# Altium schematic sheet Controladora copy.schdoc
size 711 x 428 mm
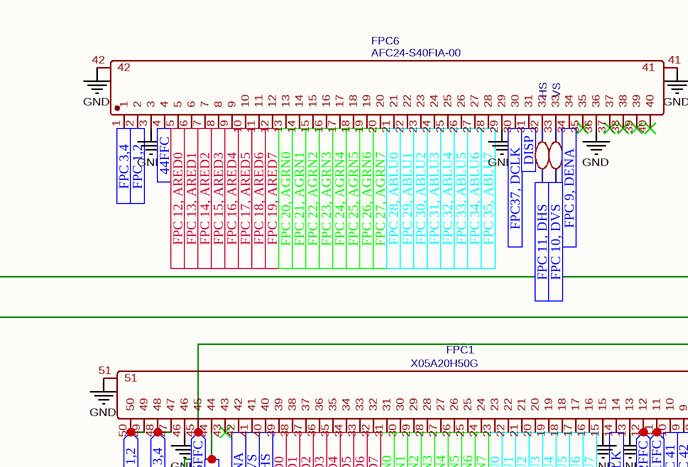
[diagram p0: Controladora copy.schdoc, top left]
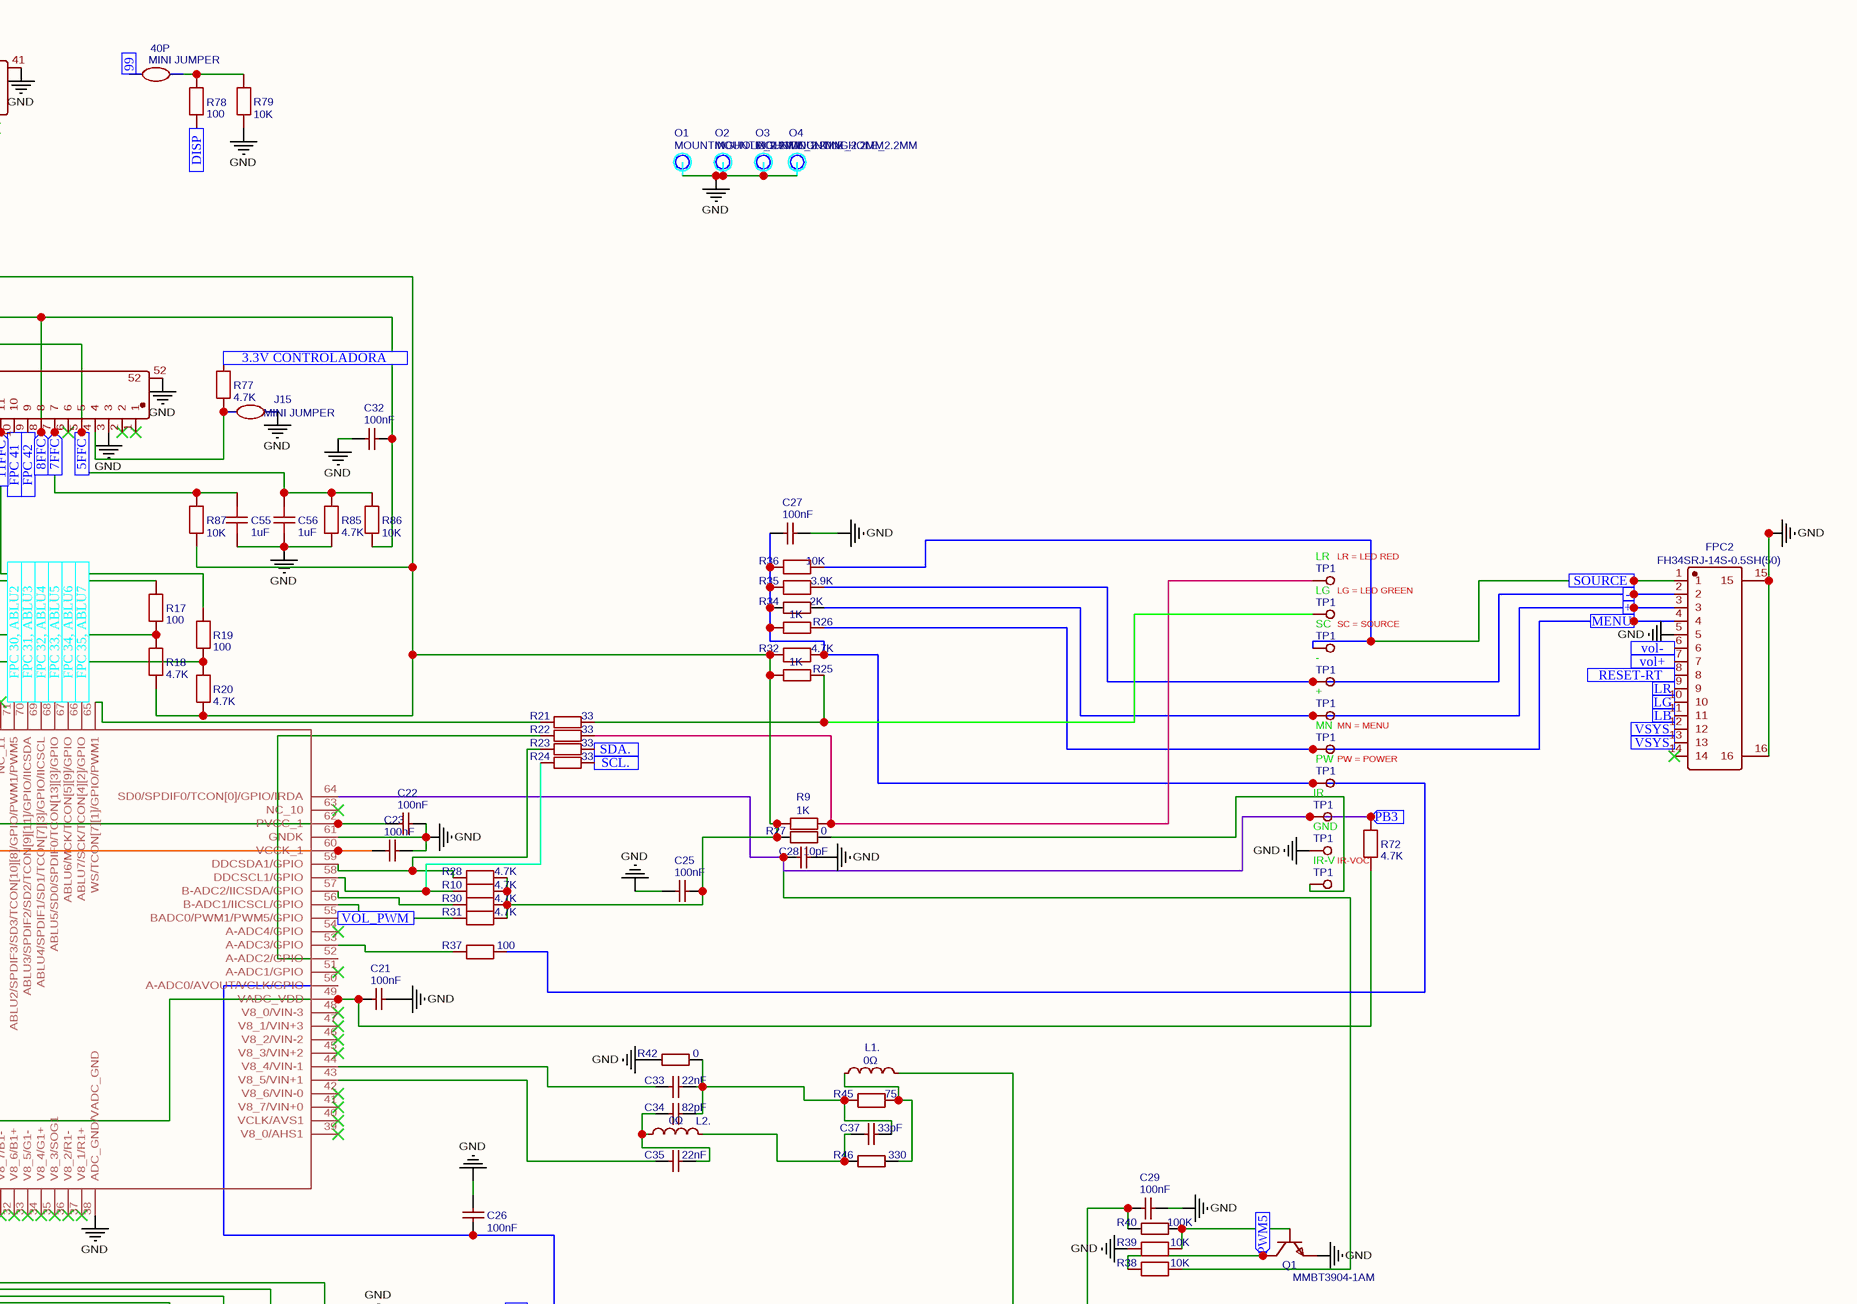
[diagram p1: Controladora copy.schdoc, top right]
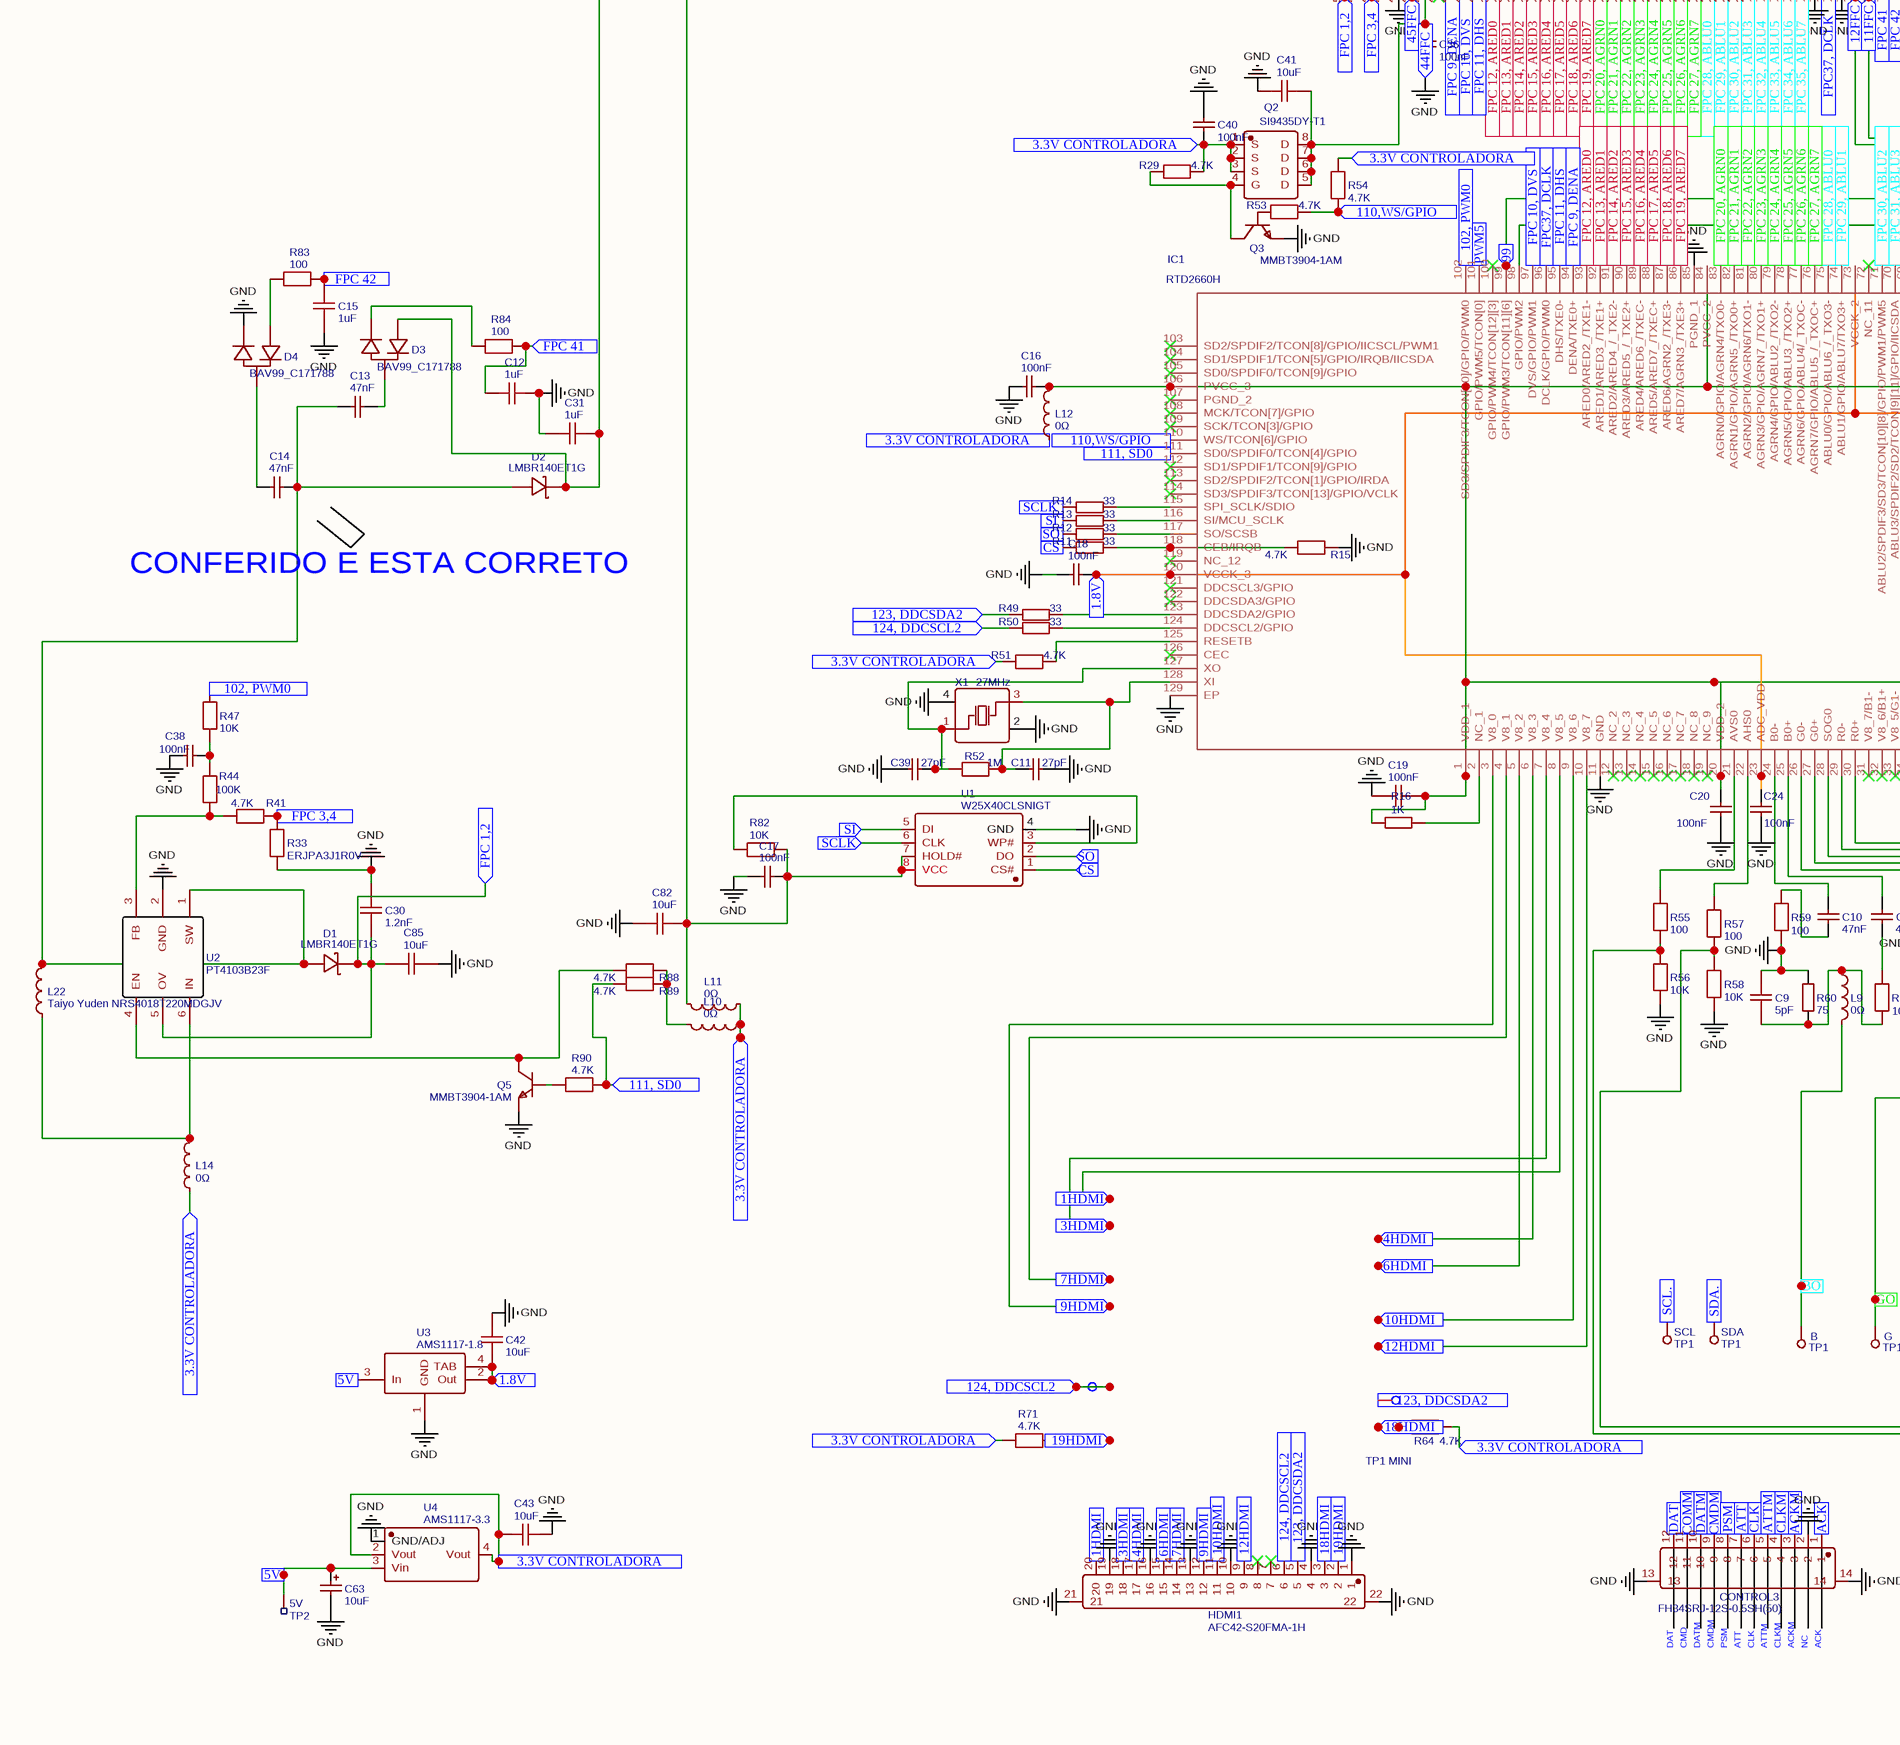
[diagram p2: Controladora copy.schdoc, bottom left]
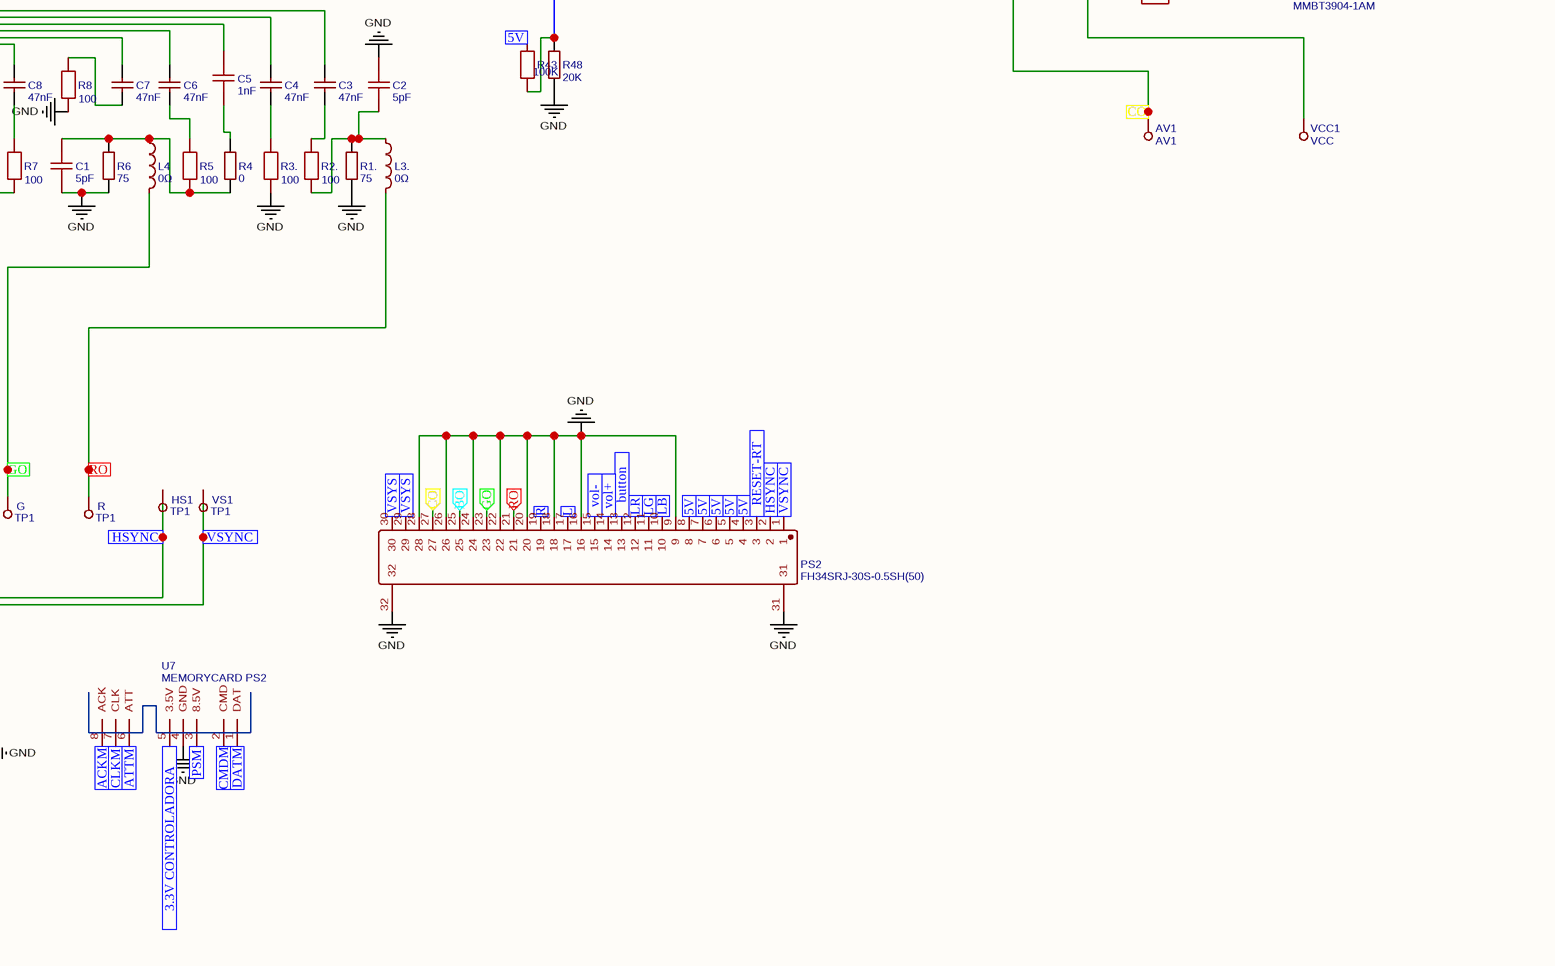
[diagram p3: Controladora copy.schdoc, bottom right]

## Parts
5V  TP2  [TP2]
40P  MINI JUMPER  [MINI JUMPER]
+  TP1  [TP1]
-  TP1  [TP1]
AV1  AV1  [TP1]
B  TP1  [TP1]
C1  5pF  [C0402]
C2  5pF  [C0402]
C3  47nF  [C0402]
C4  47nF  [C0402]
C5  1nF  [C0402]
C6  47nF  [C0402]
C7  47nF  [C0402]
C8  47nF  [C0402]
C9  5pF  [C0402]
C10  47nF  [C0402]
C11  27pF  [C0402]
C12  1uF  [C0402]
C13  47nF  [C0402]
C14  47nF  [C0402]
C15  1uF  [C0402]
C16  100nF  [C0402]
C17  100nF  [C0402]
C18  100nF  [C0402]
C19  100nF  [C0402]
C20  100nF  [C0402]
C21  100nF  [C0402]
C22  100nF  [C0402]
C23  100nF  [C0402]
C24  100nF  [C0402]
C25  100nF  [C0402]
C26  100nF  [C0402]
C27  100nF  [C0402]
C28  10pF  [C0402]
C29  100nF  [C0402]
C30  1.2nF  [C0402]
C31  1uF  [C0402]
C32  100nF  [C0402]
C33  22nF  [C0402]
C34  82pF  [C0402]
C35  22nF  [C0402]
C36  100nF  [C0402]
C37  33pF  [C0402]
C38  100nF  [C0402]
C39  27pF  [C0402]
C40  100nF  [C0402]
C41  10uF  [C0603]
C42  10uF  [C0603]
C43  10uF  [C0603]
C55  1uF  [C0402]
C56  1uF  [C0402]
C63  10uF  [CAP-SMD_L3.2-W1.6-R-RD]
C82  10uF  [C0603]
C85  10uF  [C0603]
CONTROL3  FH34SRJ-12S-0.5SH(50)  [FFC-SMD_12P-P0.50_FH34SRJ-12S-0.5SH]
D1  LMBR140ET1G  [SOD-323HE_L2.0-W1.4-LS2.5-RD]
D2  LMBR140ET1G  [SOD-323HE_L2.0-W1.4-LS2.5-RD]
D3  BAV99_C171788  [SOT-23-3_L2.9-W1.3-P1.90-LS2.4-BR]
D4  BAV99_C171788  [SOT-23-3_L2.9-W1.3-P1.90-LS2.4-BR]
FPC1  X05A20H50G  [FPC-SMD_50P-P0.50_X05A20H50G]
FPC2  FH34SRJ-14S-0.5SH(50)  [FFC-SMD_14P-P0.50_FH34SRJ-14S-0.5SH]
FPC6  AFC24-S40FIA-00  [FPC-SMD_P0.50-40P_QCHF-SM-H2.0]
G  TP1  [TP1]
GND  TP1  [TP1]
HDMI1  AFC42-S20FMA-1H  [FFC-SMD_20P-P0.50_AFC42-S20FMA-1H]
HS  MINI JUMPER  [MINI JUMPER]  (value not drawn)
HS1  TP1  [TP1]
IC1  RTD2660H  [RTD2660H]
IR  TP1  [TP1]
IR-V  TP1  [TP1]
J1  TP1 MINI  [TP1 MINI]  (value not drawn)
J2  TP1 MINI  [TP1 MINI]  (value not drawn)
J3  TP1 MINI  [TP1 MINI]  (value not drawn)
J4  TP1 MINI  [TP1 MINI]  (value not drawn)
J5  TP1 MINI  [TP1 MINI]  (value not drawn)
J6  TP1 MINI  [TP1 MINI]  (value not drawn)
J7  TP1 MINI  [TP1 MINI]  (value not drawn)
J8  TP1 MINI  [TP1 MINI]  (value not drawn)
J9  TP1 MINI  [TP1 MINI]  (value not drawn)
J10  TP1 MINI  [TP1 MINI]  (value not drawn)
J11  TP1 MINI  [TP1 MINI]  (value not drawn)
J12  TP1 MINI  [TP1 MINI]
J15  MINI JUMPER  [MINI JUMPER]
L1.  0Ω  [L0402]
L2.  0Ω  [L0402]
L3.  0Ω  [L0402]
L4  0Ω  [L0402]
L9  0Ω  [L0402]
L10  0Ω  [L0603]
L11  0Ω  [L0603]
L12  0Ω  [L0603]
L14  0Ω  [L0603]
L22  Taiyo Yuden NRS4018T220MDGJV  [NRS4018T220MDGJV  4.0X4.0X1.8MM]
LG  TP1  [TP1]
LR  TP1  [TP1]
MN  TP1  [TP1]
O1  MOUNTINGHOLE_2.2MM  [MOUNTINGHOLE_2.2MM_M2_PAD_VIA]
O2  MOUNTINGHOLE_2.2MM  [MOUNTINGHOLE_2.2MM_M2_PAD_VIA]
O3  MOUNTINGHOLE_2.2MM  [MOUNTINGHOLE_2.2MM_M2_PAD_VIA]
O4  MOUNTINGHOLE_2.2MM  [MOUNTINGHOLE_2.2MM_M2_PAD_VIA]
PS2  FH34SRJ-30S-0.5SH(50)  [FFC-SMD_30P-P0.50_FH34SRJ-30S-0.5SH]
PW  TP1  [TP1]
Q1  MMBT3904-1AM  [SOT-23-3_L3.0-W1.7-P0.95-LS2.9-BR]
Q2  SI9435DY-T1  [SO-8_L4.9-W3.9-P1.27-LS5.9-BL]
Q3  MMBT3904-1AM  [SOT-23-3_L3.0-W1.7-P0.95-LS2.9-BR]
Q5  MMBT3904-1AM  [SOT-23-3_L3.0-W1.7-P0.95-LS2.9-BR]
R  TP1  [TP1]
R1.  75  [R0402]
R2.  100  [R0402]
R3.  100  [R0402]
R4  0  [R0402]
R5  100  [R0402]
R6  75  [R0402]
R7  100  [R0402]
R8  100  [R0402]
R9  1K  [R0402]
R10  4.7K  [R0402]
R11  33  [R0402]
R12  33  [R0402]
R13  33  [R0402]
R14  33  [R0402]
R15  4.7K  [R0402]
R16  1K  [R0402]
R17  100  [R0402]
R18  4.7K  [R0402]
R19  100  [R0402]
R20  4.7K  [R0402]
R21  33  [R0402]
R22  33  [R0402]
R23  33  [R0402]
R24  33  [R0402]
R25  1K  [R0402]
R26  1K  [R0402]
R27  0  [R0402]
R28  4.7K  [R0402]
R29  4.7K  [R0402]
R30  4.7K  [R0402]
R31  4.7K  [R0402]
R32  4.7K  [R0402]
R33  ERJPA3J1R0V  [R0603]
R34  2K  [R0402]
R35  3.9K  [R0402]
R36  10K  [R0402]
R37  100  [R0402]
R38  10K  [R0402]
R39  10K  [R0402]
R40  100K  [R0402]
R41  4.7K  [R0402]
R42  0  [R0402]
R43  100K  [R0402]
R44  100K  [R0402]
R45  75  [R0402]
R46  330  [R0402]
R47  10K  [R0402]
R48  20K  [R0402]
R49  33  [R0402]
R50  33  [R0402]
R51  4.7K  [R0402]
R52  1M  [R0402]
R53  4.7K  [R0402]
R54  4.7K  [R0402]
R55  100  [R0402]
R56  10K  [R0402]
R57  100  [R0402]
R58  10K  [R0402]
R59  100  [R0402]
R60  75  [R0402]
R64  4.7K  [R0402]
R71  4.7K  [R0402]
R72  4.7K  [R0402]
R77  4.7K  [R0402]
R78  100  [R0402]
R79  10K  [R0402]
R82  10K  [R0402]
R83  100  [R0402]
R84  100  [R0402]
R85  4.7K  [R0402]
R86  10K  [R0402]
R87  10K  [R0402]
R88  4.7K  [R0402]
R89  4.7K  [R0402]
R90  4.7K  [R0402]
SC  TP1  [TP1]
SCL  TP1  [TP1]
SDA  TP1  [TP1]
U1  W25X40CLSNIGT  [SOIC-8_L5.0-W4.0-P1.27-LS6.0-BL]
U2  PT4103B23F  [SOT-23-6_L2.9-W1.6-P0.95-LS2.8-BR]
U3  AMS1117-1.8  [SOT-223-4_L6.5-W3.5-P2.30-LS7.0-BR]
U4  AMS1117-3.3  [SOT-223-3_L6.5-W3.4-P2.30-LS7.0-BR]
U7  MEMORYCARD PS2  [MEMORYCARD PS2]
VCC1  VCC  [TP1]
VS  MINI JUMPER  [MINI JUMPER]  (value not drawn)
VS1  TP1  [TP1]
X1  27MHz  [OSC-SMD_4P-L3.2-W2.5-BL]

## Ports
1.8V (in), 1HDMI (in), 3.3V CONTROLADORA (in), 3HDMI (in), 4HDMI (in), 5FFC (in), 5V (in), 6HDMI (in), 7FFC (in), 7HDMI (in), 8FFC (in), 9HDMI (in), 10HDMI (in), 11FFC (in), 12FFC (in), 12HDMI (in), 18HDMI (in), 19HDMI (in), 44FFC (in), 45FFC (in), 99 (in), 102, PWM0 (in), 110,WS/GPIO (in), 111, SD0 (in), 123, DDCSDA2 (in), 124, DDCSCL2 (in), + (in), - (in), ACK (in), ACKM (in), ATT (in), ATTM (in), BO (in), button (in), CLK (in), CLKM (in), CMDM (in), CO (in), COMM (in), CS (in), DAT (in), DATM (in), DISP (in), FPC37, DCLK (in), FPC 1,2 (in), FPC 3,4 (in), FPC 9, DENA (in), FPC 10, DVS (in), FPC 11, DHS (in), FPC 12, ARED0 (in), FPC 13, ARED1 (in), FPC 14, ARED2 (in), FPC 15, ARED3 (in), FPC 16, ARED4 (in), FPC 17, ARED5 (in), FPC 18, ARED6 (in), FPC 19, ARED7 (in), FPC 20, AGRN0 (in), FPC 21, AGRN1 (in), FPC 22, AGRN2 (in), FPC 23, AGRN3 (in), FPC 24, AGRN4 (in), FPC 25, AGRN5 (in), FPC 26, AGRN6 (in), FPC 27, AGRN7 (in), FPC 28, ABLU0 (in), FPC 29, ABLU1 (in), FPC 30, ABLU2 (in), FPC 31, ABLU3 (in), FPC 32, ABLU4 (in), FPC 33, ABLU5 (in), FPC 34, ABLU6 (in), FPC 35, ABLU7 (in), FPC 41 (in), FPC 42 (in), GO (in), HSYNC (in), L (in), LB (in), LG (in), LR (in), MENU (in), PB3 (in), PSM (in), PWM5 (in), R (in), RESET-RT (in), RO (in), SCL. (in), SCLK (in), SDA. (in), SI (in), SO (in), SOURCE (in), vol+ (in), vol- (in), VOL_PWM (in), VSYNC (in), VSYS (in)

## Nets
GND: C1.1 C2.2 C9.2 C11.2 C12.2 C15.1 C16.1 C17.1 C18.1 C19.2 C20.1 C21.2 C22.2 C23.2 C24.1 C25.1 C26.2 C27.2 C28.2 C29.2 C30.2 C31.1 C32.1 C36.1 C36.2 C38.1 C39.1 C40.2 C41.1 C41.2 C42.2 C43.1 C55.1 C56.1 C63.2 C82.1 C85.2 CONTROL3.2 CONTROL3.13 CONTROL3.14 D4.2(K) FPC1.3 FPC1.13 FPC1.15 FPC1.44 FPC1.46 FPC1.51 FPC1.52 FPC2.5 FPC2.15 FPC2.16 FPC6.3 FPC6.4 FPC6.29 FPC6.36 FPC6.41 FPC6.42 GND.1 HDMI1.1 HDMI1.4 HDMI1.10 HDMI1.13 HDMI1.16 HDMI1.19 HDMI1.21 HDMI1.22 IC1.11(GND) IC1.38(ADC_GND/VADC_GND) IC1.61(GNDK) IC1.85(PGND_1) IC1.129(EP) J15.2 O1.1 O2.1 O3.1 O4.1 PS2.9 PS2.16 PS2.18 PS2.20 PS2.22 PS2.24 PS2.26 PS2.28 PS2.31 PS2.32 Q1.2(E) Q2.5(D) Q2.6(D) Q2.7(D) Q2.8(D) Q3.2(E) Q5.2(E) R1..1 R3..1 R6.1 R8.1 R15.2 R33.1 R39.2 R42.1 R48.1 R56.1 R58.1 R59.1 R60.2 R79.1 R85.1 U1.4(GND) U2.2(GND) U3.1(GND) U4.1(GND/ADJ) U7.4(GND) X1.2(GND) X1.4(GND) ; port 44FFC
1.8V: C18.2 C23.1 C24.2 C42.1 IC1.23(ADC_VDD) IC1.60(VCCK_1) IC1.73(VCCK_2) IC1.120(VCCK_3) U3.2(Out) U3.4(TAB) ; port 1.8V
1HDMI: HDMI1.20 IC1.8(V8_5) J1.1 ; port 1HDMI
3.3V CONTROLADORA: C40.1 C43.2 L10.1 L11.1 L12.1 L14.1 Q2.1(S) Q2.2(S) Q2.3(S) R29.1 R51.2 R54.1 R64.2 R71.2 R77.2 U4.2(Vout) U4.4(Vout) U7.5(3.5V) ; port 3.3V CONTROLADORA
3HDMI: HDMI1.18 IC1.7(V8_4) J2.1 ; port 3HDMI
4HDMI: HDMI1.17 IC1.6(V8_3) J7.1 ; port 4HDMI
5V: 5V.1 C63.1 PS2.4 PS2.5 PS2.6 PS2.7 PS2.8 R43.2 U3.3(In) U4.3(Vin) ; port 5V
6HDMI: HDMI1.15 IC1.5(V8_2) J8.1 ; port 6HDMI
7FFC: C55.2 FPC1.7 R87.2 ; port 7FFC
7HDMI: HDMI1.14 IC1.4(V8_1) J3.1 ; port 7HDMI
8FFC: C31.2 C32.2 D2.1 D3.1(A) FPC1.8 R86.1 ; port 8FFC
9HDMI: HDMI1.12 IC1.3(V8_0) J4.1 ; port 9HDMI
10HDMI: HDMI1.11 IC1.9(V8_6) J9.1 ; port 10HDMI
11FFC: FPC1.11 R19.2 ; port 11FFC
12FFC: FPC1.12 R17.2 ; port 12FFC
12HDMI: HDMI1.9 IC1.10(V8_7) J10.1 ; port 12HDMI
18HDMI: HDMI1.3 J12.1 R64.1 ; port 18HDMI
19HDMI: HDMI1.2 J6.1 R71.1 ; port 19HDMI
45FFC: C56.2 FPC1.5 FPC1.45 R85.2 R86.2 ; port 45FFC, port 5FFC
99: 40P.1 IC1.99(GPIO/PWM3/TCON[11][6]) R17.1 R18.2 ; port 99
102, PWM0: IC1.102(SD3/SPDIF3/TCON[10]/GPIO/PWM0) R47.2 ; port 102, PWM0
110,WS/GPIO: IC1.110(WS/TCON[6]/GPIO) R53.1 R54.2 ; port 110,WS/GPIO
111, SD0: IC1.111(SD0/SPDIF0/TCON[4]/GPIO) R89.1 R90.2 ; port 111, SD0
123, DDCSDA2: HDMI1.5 J11.1 R49.1 ; port 123, DDCSDA2
124, DDCSCL2: HDMI1.6 J5.1 R50.1 ; port 124, DDCSCL2
+: +.1 FPC2.3 R34.2 ; port +
-: -.1 FPC2.2 R35.2 ; port -
ACK: CONTROL3.1 ; port ACK
ACKM: CONTROL3.3 U7.8(ACK) ; port ACKM
ATT: CONTROL3.7 ; port ATT
ATTM: CONTROL3.5 U7.6(ATT) ; port ATTM
BO: B.1 L9.2 PS2.25 ; port BO
button: PS2.13 ; port button
CLK: CONTROL3.6 ; port CLK
CLKM: CONTROL3.4 U7.7(CLK) ; port CLKM
CMDM: CONTROL3.9 U7.2(CMD) ; port CMDM
CO: AV1.1 L1..2 PS2.27 ; port CO
COMM: CONTROL3.11 ; port COMM
CS: R11.1 U1.1(CS#) ; port CS
DAT: CONTROL3.12 ; port DAT
DATM: CONTROL3.10 U7.1(DAT) ; port DATM
DISP: FPC6.31 R78.1 ; port DISP
FPC37, DCLK: FPC1.14 FPC6.30 IC1.96(DCLK/GPIO/PWM0) ; port FPC37, DCLK
FPC 1,2: C30.1 C85.1 D1.1 FPC1.49 FPC1.50 FPC6.2 U2.5(OV) ; port FPC 1,2
FPC 3,4: FPC1.47 FPC1.48 FPC6.1 R33.2 R41.2 ; port FPC 3,4
FPC 9, DENA: FPC1.42 FPC6.34 IC1.94(DENA/TXE0+) ; port FPC 9, DENA
FPC 10, DVS: FPC1.41 IC1.97(DVS/GPIO/PWM1) VS.1 ; port FPC 10, DVS
FPC 11, DHS: FPC1.40 HS.1 IC1.95(DHS/TXE0-) ; port FPC 11, DHS
FPC 12, ARED0: FPC1.39 FPC6.5 IC1.93(ARED0/ARED2_/TXE1-) ; port FPC 12, ARED0
FPC 13, ARED1: FPC1.38 FPC6.6 IC1.92(ARED1/ARED3_/TXE1+) ; port FPC 13, ARED1
FPC 14, ARED2: FPC1.37 FPC6.7 IC1.91(ARED2/ARED4_/_TXE2-) ; port FPC 14, ARED2
FPC 15, ARED3: FPC1.36 FPC6.8 IC1.90(ARED3/ARED5_/_TXE2+) ; port FPC 15, ARED3
FPC 16, ARED4: FPC1.35 FPC6.9 IC1.89(ARED4/ARED6_/TXEC-) ; port FPC 16, ARED4
FPC 17, ARED5: FPC1.34 FPC6.10 IC1.88(ARED5/ARED7_/TXEC+) ; port FPC 17, ARED5
FPC 18, ARED6: FPC1.33 FPC6.11 IC1.87(ARED6/AGRN2_/TXE3-) ; port FPC 18, ARED6
FPC 19, ARED7: FPC1.32 FPC6.12 IC1.86(ARED7/AGRN3_/TXE3+) ; port FPC 19, ARED7
FPC 20, AGRN0: FPC1.31 FPC6.13 IC1.83(AGRN0/GPIO/AGRN4/TXO0-) ; port FPC 20, AGRN0
FPC 21, AGRN1: FPC1.30 FPC6.14 IC1.82(AGRN1/GPIO/AGRN5_/TXO0+) ; port FPC 21, AGRN1
FPC 22, AGRN2: FPC1.29 FPC6.15 IC1.81(AGRN2/GPIO/AGRN6/TXO1-) ; port FPC 22, AGRN2
FPC 23, AGRN3: FPC1.28 FPC6.16 IC1.80(AGRN3/GPIO/AGRN7_/TXO1+) ; port FPC 23, AGRN3
FPC 24, AGRN4: FPC1.27 FPC6.17 IC1.79(AGRN4/GPIO/ABLU2_/TXO2-) ; port FPC 24, AGRN4
FPC 25, AGRN5: FPC1.26 FPC6.18 IC1.78(AGRN5/GPIO/ABLU3_/TXO2+) ; port FPC 25, AGRN5
FPC 26, AGRN6: FPC1.25 FPC6.19 IC1.77(AGRN6/GPIO/ABLU4/_TXOC-) ; port FPC 26, AGRN6
FPC 27, AGRN7: FPC1.24 FPC6.20 IC1.76(AGRN7/GPIO/ABLU5_/_TXOC+) ; port FPC 27, AGRN7
FPC 28, ABLU0: FPC1.23 FPC6.21 IC1.75(ABLU0/GPIO/ABLU6_/_TXO3-) ; port FPC 28, ABLU0
FPC 29, ABLU1: FPC1.22 FPC6.22 IC1.74(ABLU1/GPIO/ABLU7/TXO3+) ; port FPC 29, ABLU1
FPC 30, ABLU2: FPC1.21 FPC6.23 IC1.71(ABLU2/SPDIF3/SD3/TCON[10][8]/GPIO/PWM1/PWM5) ; port FPC 30, ABLU2
FPC 31, ABLU3: FPC1.20 FPC6.24 IC1.70(ABLU3/SPDIF2/SD2/TCON[9][11]/GPIO/IICSDA) ; port FPC 31, ABLU3
FPC 32, ABLU4: FPC1.19 FPC6.25 IC1.69(ABLU4/SPDIF1/SD1/TCON[7][3]/GPIO/IICSCL) ; port FPC 32, ABLU4
FPC 33, ABLU5: FPC1.18 FPC6.26 IC1.68(ABLU5/SD0/SPDIF0/TCON[13][3]/GPIO) ; port FPC 33, ABLU5
FPC 34, ABLU6: FPC1.17 FPC6.27 IC1.67(ABLU6/MCK/TCON[5][9]/GPIO) ; port FPC 34, ABLU6
FPC 35, ABLU7: FPC1.16 FPC6.28 IC1.66(ABLU7/SCK/TCON[4][2]/GPIO) ; port FPC 35, ABLU7
FPC 41: C12.1 FPC1.10 R84.2 ; port FPC 41
FPC 42: C15.2 FPC1.9 R83.2 ; port FPC 42
GO: G.1 L4.2 PS2.23 ; port GO
HSYNC: HS1.1 PS2.2 R57.1 R58.2 ; port HSYNC
L: PS2.17 ; port L
LB: FPC2.11 PS2.10 ; port LB
LG: FPC2.10 PS2.11 ; port LG
LR: FPC2.9 PS2.12 ; port LR
MENU: FPC2.4 MN.1 R26.2 ; port MENU
PB3: C28.1 IC1.64(SD0/SPDIF0/TCON[0]/GPIO/IRDA) IR.1 R38.1 R72.1 ; port PB3
PSM: CONTROL3.8 U7.3(8.5V) ; port PSM
PWM5: IC1.101(GPIO/PWM5/TCON[0]) Q1.3(C) R38.2 ; port PWM5
R: PS2.19 ; port R
RESET-RT: FPC2.8 PS2.3 ; port RESET-RT
RO: L3..2 PS2.21 R.1 ; port RO
SCL.: R24.2 SCL.1 ; port SCL.
SCLK: R14.1 U1.6(CLK) ; port SCLK
SDA.: R23.2 SDA.1 ; port SDA.
SI: R13.1 U1.5(DI) ; port SI
SO: R12.1 U1.2(DO) ; port SO
SOURCE: FPC2.1 R36.1 SC.1 ; port SOURCE
vol+: FPC2.7 PS2.14 ; port vol+
vol-: FPC2.6 PS2.15 ; port vol-
VOL_PWM: IC1.55(BADC0/PWM1/PWM5/GPIO) IC1.56(B-ADC1/IICSCL/GPIO) R31.2 ; port VOL_PWM
VSYNC: PS2.1 R55.1 R56.2 VS1.1 ; port VSYNC
VSYS: FPC2.12 FPC2.13 PS2.29 PS2.30 ; port VSYS
Net40P_2: 40P.2 R78.2 R79.2
NetC1_2: C1.2 L4.1 R4.1 R5.1 R6.2
NetC2_1: C2.1 L3..1 R1..2 R2..1
NetC3_1: C3.1 R2..2
NetC3_2: C3.2 IC1.30(R0+)
NetC4_1: C4.1 R3..2
NetC4_2: C4.2 IC1.29(R0-)
NetC5_1: C5.1 R4.2
NetC5_2: C5.2 IC1.28(SOG0)
NetC6_1: C6.1 R5.2
NetC6_2: C6.2 IC1.27(G0+)
NetC7_1: C7.1 R8.2
NetC7_2: C7.2 IC1.26(G0-)
NetC8_1: C8.1 R7.2
NetC8_2: C8.2 IC1.25(B0+)
NetC9_1: C9.1 L9.1 R7.1 R60.1
NetC10_1: C10.1 R59.2
NetC10_2: C10.2 IC1.24(B0-)
NetC11_1: C11.1 IC1.128(XI) R52.2 X1.3(OSC2)
NetC13_1: C13.1 C14.2 D1.2 D2.2 L22.2 U2.1(SW)
NetC13_2: C13.2 D3.3(COM)
NetC14_1: C14.1 D4.3(COM)
NetC16_2: C16.2 C19.1 C20.2 C21.1 C22.1 IC1.1(VDD_1) IC1.20(VDD_2) IC1.49(VADC_VDD) IC1.62(PVCC_1) IC1.84(PVCC_2) IC1.106(PVCC_3) L12.2 R16.1 R72.2
NetC17_2: C17.2 C25.2 C82.2 L11.2 R9.1 R10.1 R18.1 R20.1 R25.1 R27.1 R28.1 R30.1 R31.1 R32.2 R82.1 R87.1 U1.7(HOLD#) U1.8(VCC)
NetC26_1: C26.1 IC1.50(A-ADC0/AVOUT/VCLK/GPIO) R43.1 R48.2
NetC27_1: C27.1 PW.1 R26.1 R32.1 R34.1 R35.1 R36.2 R37.2
NetC29_1: C29.1 R40.1 VCC1.1
NetC33_1: C33.1 IC1.44(V8_4/VIN-1)
NetC33_2: C33.2 C34.2 C37.2 R42.2 R45.1
NetC34_1: C34.1 C35.2 L2..1
NetC35_1: C35.1 IC1.43(V8_5/VIN+1)
NetC37_1: C37.1 L2..2 R46.1
NetC38_2: C38.2 R44.2 R47.1
NetC39_2: C39.2 IC1.127(XO) R52.1 X1.1(OSC1)
NetD3_2: D3.2(K) R84.1
NetD4_1: D4.1(A) R83.1
NetFPC1_4: FPC1.4 J15.1 R77.1
NetFPC6_32: FPC6.32 HS.2
NetFPC6_33: FPC6.33 VS.2
NetIC1_2: IC1.2(NC_1) R16.2
NetIC1_21: IC1.21(AVS0) R55.2
NetIC1_22: IC1.22(AHS0) R57.2
NetIC1_52: IC1.52(A-ADC2/GPIO) R22.1
NetIC1_53: IC1.53(A-ADC3/GPIO) R37.1
NetIC1_57: IC1.57(B-ADC2/IICSDA/GPIO) R30.2
NetIC1_58: IC1.58(DDCSCL1/GPIO) R10.2 R24.1
NetIC1_59: IC1.59(DDCSDA1/GPIO) R23.1 R28.2
NetIC1_65: IC1.65(WS/TCON[7][1]/GPIO/PWM1) R21.1
NetIC1_98: IC1.98(GPIO/PWM2) R19.1 R20.2
NetIC1_115: IC1.115(SPI_SCLK/SDIO) R14.2
NetIC1_116: IC1.116(SI/MCU_SCLK) R13.2
NetIC1_117: IC1.117(SO/SCSB) R12.2
NetIC1_118: IC1.118(CEB/IRQB) R11.2 R15.1
NetIC1_123: IC1.123(DDCSDA2/GPIO) R49.2
NetIC1_124: IC1.124(DDCSCL2/GPIO) R50.2
NetIC1_125: IC1.125(RESETB) R51.1
NetIR-V_1: IR-V.1 R27.2
NetL1._1: L1..1 R45.2 R46.2
NetL10_2: L10.2 R88.2 R89.2
NetL14_2: L14.2 L22.1 U2.6(IN)
NetLG_1: LG.1 R21.2 R25.2
NetLR_1: LR.1 R9.2 R22.2
NetQ1_1: Q1.1(B) R39.1 R40.2
NetQ2_4: Q2.4(G) Q3.3(C) R29.2
NetQ3_1: Q3.1(B) R53.2
NetQ5_1: Q5.1(B) R90.1
NetQ5_3: Q5.3(C) R88.1 U2.4(EN)
NetR41_1: R41.1 R44.1 U2.3(FB)
NetR82_2: R82.2 U1.3(WP#)

Not connected (* = marked no-connect by the designer): FPC1 1* 2* 6* 43*; FPC2 14*; FPC6 35* 37* 38* 39* 40*; HDMI1 7* 8*; IC1 12(NC_2)* 13(NC_3)* 14(NC_4)* 15(NC_5)* 16(NC_6)* 17(NC_7)* 18(NC_8)* 19(NC_9)* 31(V8_7/B1-)* 32(V8_6/B1+)* 33(V8_5/G1-)* 34(V8_4/G1+)* 35(V8_3/SOG1)* 36(V8_2/R1-)* 37(V8_1/R1+)* 39(V8_0/AHS1)* 40(VCLK/AVS1)* 41(V8_7/VIN+0)* 42(V8_6/VIN-0)* 45(V8_3/VIN+2)* 46(V8_2/VIN-2)* 47(V8_1/VIN+3)* 48(V8_0/VIN-3)* 51(A-ADC1/GPIO)* 54(A-ADC4/GPIO)* 63(NC_10)* 72(NC_11)* 100(GPIO/PWM4/TCON[12][3])* 103(SD2/SPDIF2/TCON[8]/GPIO/IICSCL/PWM1)* 104(SD1/SPDIF1/TCON[5]/GPIO/IRQB/IICSDA)* 105(SD0/SPDIF0/TCON[9]/GPIO)* 107(PGND_2)* 108(MCK/TCON[7]/GPIO)* 109(SCK/TCON[3]/GPIO)* 112(SD1/SPDIF1/TCON[9]/GPIO)* 113(SD2/SPDIF2/TCON[1]/GPIO/IRDA)* 114(SD3/SPDIF3/TCON[13]/GPIO/VCLK)* 119(NC_12)* 121(DDCSCL3/GPIO)* 122(DDCSDA3/GPIO)* 126(CEC)*

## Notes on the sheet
- (near LR) LR = LED RED
- LG = LED GREEN
- SC = SOURCE
- MN = MENU
- PW = POWER
- IR-VOC
- CONFERIDO E ESTA CORRETO
- DAT
- CMD
- (near CONTROL3) DATM
- (near CONTROL3) CMDM
- PSM
- ATT
- CLK
- (near CONTROL3) ATTM
- (near CONTROL3) CLKM
- (near CONTROL3) ACKM
- NC
- ACK

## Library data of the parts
5V = TP2: Contributor: Marlon Vinicius
40P HS J15 VS = MINI JUMPER: Contributor: Marlon Vinicius
+ - B G GND HS1 IR IR-V LG LR MN PW R SC SCL SDA VS1 = TP1: Contributor: Marlon Vinicius
AV1 = AV1: Contributor: Marlon Vinicius
C1 C2 C9 = 5pF: Manufacturer: YAGEO; Manufacturer Part: CC0402CRNPO9BN5R0; nameAlias: Capacitance; Contributor: LCSC
C3 C4 C6-C8 C10 = 47nF: Manufacturer Part: GRM155R71C473KA01D; Manufacturer: MuRata; nameAlias: Capacitance
C5 = 1nF: Manufacturer: YAGEO; Manufacturer Part: CC0402JRNPO8BN102; nameAlias: Capacitance; Contributor: LCSC
C11 C39 = 27pF: Manufacturer: MuRata; Manufacturer Part: GCM1555C1H270JA16D; nameAlias: Capacitance
C12 C15 C31 C55 C56 = 1uF: Manufacturer: SAMSUNG; Manufacturer Part: CL05A105KA5NQNC; nameAlias: Capacitance
C13 C14 = 47nF: Manufacturer: YAGEO; Manufacturer Part: CC0402KRX7R8BB473; nameAlias: Capacitance; Paste Type: Extended Part
C16-C18 C20-C27 C29 C32 C36 C38 C40 = 100nF: Manufacturer: YAGEO; Manufacturer Part: CC0402KRX7R8BB104; nameAlias: Capacitance; Contributor: LCSC
C19 = 100nF: Manufacturer: YAGEO; Manufacturer Part: CC0402JRX7R6BB104; nameAlias: Capacitance; Contributor: LCSC
C28 = 10pF: Manufacturer: YAGEO; Manufacturer Part: CC0402JRNPO9BN100; nameAlias: Capacitance
C30 = 1.2nF: Manufacturer: Huaxin S&T; Manufacturer Part: 0402B122M500CT; nameAlias: Capacitance; Contributor: LCSC
C33 C35 = 22nF: Manufacturer: YAGEO; Manufacturer Part: CC0402KRX7R9BB223; nameAlias: Capacitance
C34 = 82pF: Manufacturer: YAGEO; Manufacturer Part: CC0402JRNPO9BN820; nameAlias: Capacitance
C37 = 33pF: Manufacturer Part: CL05C330JB5NNNC; Manufacturer: SAMSUNG; nameAlias: Capacitance
C41-C43 C82 C85 = 10uF: Manufacturer: SAMSUNG; Manufacturer Part: CL10A106MA8NRNC; nameAlias: Capacitance
C63 = 10uF: Manufacturer: AVX; Manufacturer Part: TAJA106K010RNJ; nameAlias: Capacitance
CONTROL3 = FH34SRJ-12S-0.5SH(50): Manufacturer: Hirose; Contributor: LCSC
D1 D2 = LMBR140ET1G: Manufacturer: Leshan Radio; Contributor: LCSC
D3 D4 = BAV99_C171788: Manufacturer: Sangdest Microelectronicstronic (Nanjing); Manufacturer Part: BAV99; Contributor: LCSC; SMT Type: Extend
FPC1 = X05A20H50G: Manufacturer: XKB Enterprise; Contributor: LCSC
FPC2 = FH34SRJ-14S-0.5SH(50): Manufacturer: Hirose; Contributor: LCSC
FPC6 = AFC24-S40FIA-00: Manufacturer: JUSHUO; Contributor: LCSC
HDMI1 = AFC42-S20FMA-1H: Manufacturer: JUSHUO; Contributor: LCSC
IC1 = RTD2660H: Contributor: Marlon Vinicius
J1-J12 = TP1 MINI: Contributor: Marlon Vinicius
L1. L2. L3. L4 L9 = 0Ω: Manufacturer: FH; Manufacturer Part: CBG100505U000T; nameAlias: Value
L10-L12 L14 = 0Ω: Manufacturer: FH; Manufacturer Part: CBW160808U000T; nameAlias: Value; Paste Type: Extended Part
L22 = Taiyo Yuden NRS4018T220MDGJV: Contributor: Marlon Vinicius
O1-O4 = MOUNTINGHOLE_2.2MM: Contributor: Marlon Vinicius
PS2 = FH34SRJ-30S-0.5SH(50): Manufacturer: Hirose; Contributor: LCSC
Q1 Q3 Q5 = MMBT3904-1AM: Manufacturer: (MDD) Jiangsu Yutai Elec; Contributor: LCSC; SMT Type: Extend
Q2 = SI9435DY-T1: Manufacturer: VBsemi Elec; Contributor: LCSC
R1. R6 R60 = 75: Manufacturer: YAGEO; Manufacturer Part: RC0402JR-0775RL; nameAlias: Resistance (Ohms)
R2. R3. R5 R7 R8 R17 R19 R37 R55 R57 R59 R78 R83 R84 = 100: Manufacturer: PANASONIC; Manufacturer Part: ERJPA2J101X; nameAlias: Resistance (Ohms); Contributor: LCSC
R4 R27 R42 = 0: Manufacturer: YAGEO; Manufacturer Part: RC0402FR-070RL; nameAlias: Resistance (Ohms)
R9 R16 R25 R26 = 1K: Manufacturer: YAGEO; Manufacturer Part: AC0402FR-071KL; nameAlias: Resistance (Ohms); Contributor: LCSC; Resistance: 1kΩ
R10 R15 R18 R20 R28-R32 R41 R51 R53 R54 R64 R71 R72 R77 R85 R88-R90 = 4.7K: Manufacturer: PANASONIC; Manufacturer Part: ERJPA2F4701X; nameAlias: Resistance (Ohms); Contributor: LCSC
R11-R14 R21-R24 R49 R50 = 33: Manufacturer: PANASONIC; Manufacturer Part: ERJ2RKF33R0X; nameAlias: Resistance (Ohms); Contributor: LCSC
R33 = ERJPA3J1R0V: Manufacturer: PANASONIC; Contributor: LCSC
R34 = 2K: Manufacturer: YAGEO; Manufacturer Part: RC0402FR-072KL; nameAlias: Resistance (Ohms)
R35 = 3.9K: Manufacturer: PANASONIC; Manufacturer Part: ERJ2RKF3901X; nameAlias: Resistance (Ohms); Contributor: LCSC
R36 R38 R39 R47 R56 R58 R79 R82 R86 R87 = 10K: Manufacturer: PANASONIC; Manufacturer Part: ERJPA2F1002X; nameAlias: Resistance (Ohms); Contributor: LCSC
R40 = 100K: Manufacturer: YAGEO; Manufacturer Part: RC0402FR-07100KL; nameAlias: Resistance (Ohms)
R43 R44 = 100K: Manufacturer: PANASONIC; Manufacturer Part: ERJPA2J104X; nameAlias: Resistance (Ohms); Contributor: LCSC
R45 = 75: Manufacturer: PANASONIC; Manufacturer Part: ERJ2RKF75R0X; nameAlias: Resistance (Ohms); Contributor: LCSC
R46 = 330: Manufacturer: UniOhm; Manufacturer Part: 0402WGF3300TCE; nameAlias: Resistance (Ohms)
R48 = 20K: Manufacturer: YAGEO; Manufacturer Part: RC0402JR-0720KL; nameAlias: Resistance (Ohms); Contributor: LCSC
R52 = 1M: Manufacturer: PANASONIC; Manufacturer Part: ERJPA2J105X; nameAlias: Resistance (Ohms); Contributor: LCSC
U1 = W25X40CLSNIGT: Manufacturer: WINBOND
U2 = PT4103B23F: Manufacturer: PowTech
U3 = AMS1117-1.8: Manufacturer: AMS
U4 = AMS1117-3.3: Manufacturer: AMS; sourceId: dwIGgezVh
U7 = MEMORYCARD PS2: Contributor: linkmarlonvrb
VCC1 = VCC: Contributor: Marlon Vinicius
X1 = 27MHz: Manufacturer: YXC; Manufacturer Part: X322527MSB4SI; nameAlias: Frequency; Paste Type: Extended Part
